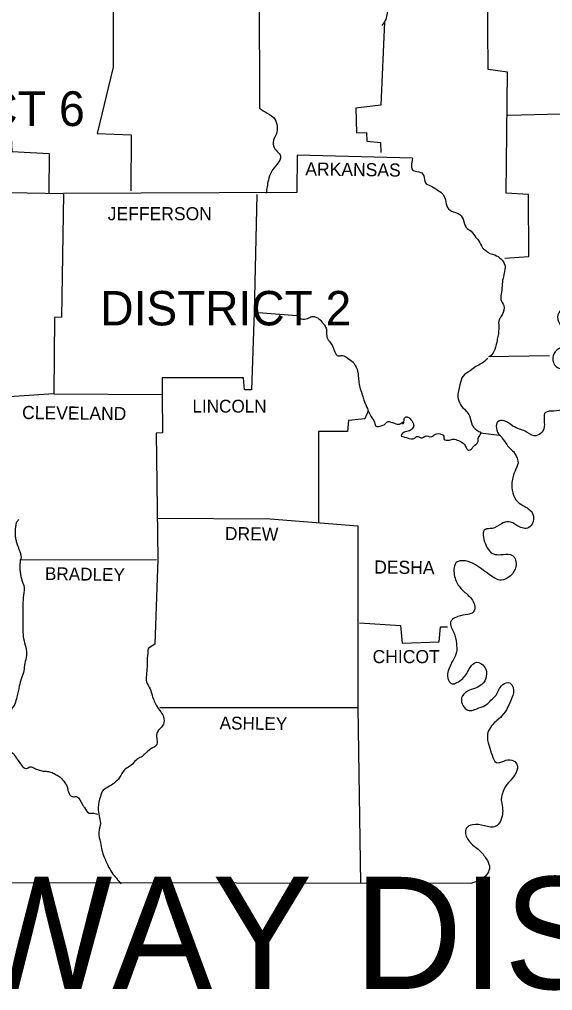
# Model space of a CAD drawing. Extents: x -43543 to 34500, y -13675 to 11152.
# Drawn here: x 13557 to 15268, y 4715 to 7833 of the extents above; entities that cross this region are included whole.
import ezdxf

# ---------------------------------------------------------------- set-up
doc = ezdxf.new("R2010")
doc.units = 0
for name, color, linetype in [('1', 7, 'Continuous'), ('2', 7, 'Continuous'), ('3', 7, 'Continuous')]:
    doc.layers.add(name, color=color, linetype=linetype)

msp = doc.modelspace()

# ---------------------------------------------------------------- linework, layer by layer
at = {"layer": '1'}
msp.add_line((15062.2, 6750.6), (15257.9, 6753.5), dxfattribs=at)
for points in [[(14186.6, 8101.8), (14188.5, 7926.6), (14326.5, 7923.7), (14327.4, 7548)], [(13800.1, 8056.8), (13856.8, 8052.9), (13857.8, 7679.1), (13806.9, 7466.8), (13915.5, 7461.9), (13914.6, 7281.9)], [(15115.1, 7066.6), (15191.4, 7071.5), (15190.4, 7270.1), (15119, 7275), (15122.9, 7663.4), (15061.3, 7672.3), (15059.3, 7933.5), (15893.9, 7939.4)], [(14728.6, 7824.9), (14716.9, 7556.8), (14636.6, 7548), (14638.6, 7468.7), (14670.9, 7469.7), (14671.8, 7442.3), (14715.9, 7437.4), (14716.9, 7405.1)], [(13044.8, 7812.2), (13154.3, 7805.3), (13150.4, 7683), (13278.6, 7678.1), (13280.6, 7571.5), (13341.2, 7566.6), (13341.2, 7548), (13398, 7544.1), (13399.9, 7475.6), (13529.1, 7475.6), (13533, 7408.1), (13652.3, 7402.2), (13651.4, 7275)], [(15124.9, 7525.5), (15676.7, 7539.2)], [(14818.6, 7387.5), (14448.8, 7397.3), (14446.8, 7277), (13698.3, 7274)], [(13134.8, 7144.9), (13189.6, 7152.7), (13193.5, 7186), (13225.8, 7191.9), (13227.7, 7211.4), (13455.7, 7218.3), (13464.5, 7278), (13698.3, 7274)], [(13698.3, 7272.1), (13692.5, 6876.8), (13670, 6875.8), (13667, 6630.3)], [(14318.6, 7271.1), (14310.8, 6892.5), (14446.8, 6881.7)], [(14310.8, 6892.5), (14302, 6643.9), (14279.5, 6643.9), (14275.6, 6682.1), (14015.3, 6682.1), (14015.3, 6627.3)], [(13667, 6630.3), (13524.2, 6621.4)], [(13667, 6630.3), (14015.3, 6628.3)], [(14015.3, 6628.3), (14016.3, 6506), (13995.8, 6505), (14001.6, 6099)], [(14676.7, 6576.4), (14665, 6550), (14613.1, 6545.1), (14610.2, 6509.9), (14517.3, 6509.9), (14516.3, 6217.4)], [(14786.3, 6533.4), (14789.3, 6536.3), (14792.2, 6539.3), (14792.2, 6539.3)], [(13998.7, 6232), (14361.7, 6229.1), (14643.5, 6207.6)], [(14643.5, 6207.6), (14643.5, 5622.5), (14651.3, 5059.9)], [(13559.4, 6098), (13996.5, 6099)], [(14001.6, 6099), (13991.9, 5827), (13970.3, 5813.3)], [(14648.4, 5895.5), (14779.5, 5887.6), (14785.3, 5830.9), (14903.7, 5834.8), (14908.6, 5882.7), (14931.1, 5882.7)], [(14007.5, 5623.5), (14643.5, 5623.5)], [(12742, 5063.6), (15008.4, 5059.9)]]:
    msp.add_lwpolyline(points, dxfattribs=at)
for points in [[(14717.8, 7918.8), (14713.9, 7899.2), (14721.7, 7878.7), (14735.4, 7871.8), (14737.4, 7852.3), (14732.5, 7832.7), (14728.6, 7824.9), (14719.8, 7813.1)], [(15832.2, 7702.6), (15809.7, 7674.2), (15776.5, 7691.8), (15776.5, 7715.3), (15781.4, 7739.8), (15769.6, 7755.4), (15749.1, 7748.6), (15749.1, 7718.2), (15747.1, 7688.9), (15741.2, 7646.8), (15754.9, 7634.1), (15786.3, 7630.2), (15808.8, 7624.3), (15822.5, 7601.8), (15821.5, 7574.4), (15810.7, 7548), (15795.1, 7526.5), (15770.6, 7518.6), (15751, 7531.4), (15743.2, 7556.8), (15734.4, 7579.3), (15717.8, 7595.9), (15700.2, 7577.3), (15696.2, 7543.1), (15697.2, 7513.8), (15697.2, 7473.6), (15722.7, 7447.2), (15738.3, 7416.9), (15733.4, 7389.5), (15714.8, 7357.2), (15707, 7328.8), (15699.2, 7290.7), (15700.2, 7248.6), (15693.3, 7207.5), (15679.6, 7180.1), (15654.2, 7157.6), (15637.5, 7142.9), (15623.8, 7128.3), (15617, 7098.9), (15612.1, 7078.4), (15593.5, 7053.9), (15578.8, 7051.9), (15567.1, 7061.7), (15563.2, 7078.4), (15563.2, 7095), (15555.4, 7111.6), (15530.9, 7118.5), (15511.3, 7117.5), (15502.5, 7103.8), (15515.2, 7065.6), (15520.1, 7041.2), (15513.3, 7007.9), (15517.2, 7004), (15482, 6985.4), (15453.6, 6982.5), (15430.1, 6975.6), (15407.6, 6961), (15396.8, 6939.4), (15381.2, 6921.8), (15367.5, 6905.2), (15348.9, 6897.4), (15328.4, 6901.3), (15301, 6904.2), (15285.3, 6884.6), (15290.2, 6856.3), (15308.8, 6839.6), (15336.2, 6831.8), (15364.6, 6833.8), (15392, 6836.7), (15417.4, 6823), (15412.5, 6796.6), (15388, 6783.9), (15351.8, 6779.9), (15322.5, 6782.9), (15287.3, 6775.1), (15269.7, 6752.6), (15279.4, 6718.3), (15317.6, 6704.6), (15335.2, 6672.3), (15336.2, 6642), (15323.5, 6601.9), (15305.9, 6583.3), (15271.6, 6575.5), (15245.2, 6570.6), (15241.3, 6525.6), (15229.5, 6503.1), (15209, 6496.2), (15179.6, 6510.9), (15162, 6517.7), (15140.5, 6527.5), (15113.1, 6544.2), (15092.6, 6541.2), (15098.4, 6498.2), (15100.4, 6496.2), (15123.9, 6463.9), (15147.4, 6438.5), (15158.1, 6408.2)], [(14327.4, 7548), (14351.9, 7531.4), (14377.3, 7511.8), (14384.2, 7485.4), (14382.2, 7466.8), (14374.4, 7451.1), (14372.5, 7426.7), (14384.2, 7409.1), (14395, 7394.4), (14384.2, 7368), (14365.6, 7343.5), (14355.8, 7316.1), (14349, 7275)], [(14818.6, 7387.5), (14821.5, 7347.4), (14845, 7341.6), (14854.8, 7330.8), (14859.7, 7308.3), (14876.3, 7298.5), (14898.8, 7284.8), (14912.5, 7275), (14922.3, 7259.4), (14928.2, 7233.9), (14943.8, 7217.3), (14965.4, 7209.5), (14981, 7190.9), (14990.8, 7164.5), (15006.5, 7152.7), (15022.1, 7132.2), (15029.9, 7123.4), (15043.6, 7099.9), (15057.3, 7088.1), (15067.1, 7081.3), (15082.8, 7076.4), (15102.3, 7063.7), (15115.1, 7044.1), (15115.1, 7029.4), (15110.2, 7006.9), (15106.3, 6983.5), (15104.3, 6957), (15102.3, 6933.6), (15111.2, 6914), (15106.3, 6884.6), (15096.5, 6869), (15095.5, 6847.5), (15092.6, 6815.2), (15088.7, 6796.6), (15079.8, 6766.2), (15067.1, 6750.6)], [(14446.8, 6881.7), (14461.5, 6871.9), (14482, 6872.9), (14495.7, 6878.8), (14506.5, 6877.8), (14521.2, 6869), (14531, 6857.2), (14537.8, 6848.4), (14542.7, 6834.7), (14542.7, 6822), (14547.6, 6804.4), (14553.5, 6797.6), (14561.3, 6784.8), (14566.2, 6773.1), (14569.1, 6765.3), (14579.9, 6752.6), (14589.7, 6753.5), (14598.5, 6752.6), (14610.2, 6745.7), (14627.8, 6732), (14630.8, 6728.1), (14642.5, 6702.7), (14644.5, 6687), (14646.4, 6666.5), (14650.3, 6646.9), (14658.2, 6625.4), (14662.1, 6610.7), (14670.9, 6590.1), (14676.7, 6576.4), (14684.6, 6558.8), (14696.3, 6539.3), (14701.2, 6527.5), (14717.8, 6528.5), (14729.6, 6533.4), (14738.4, 6541.2), (14749.1, 6540.2), (14760.9, 6536.3), (14776.5, 6533.4), (14786.3, 6539.3), (14791.2, 6543.2), (14792.2, 6552), (14801, 6556.9), (14810.8, 6550), (14821.5, 6534.4), (14821.5, 6524.6), (14817.6, 6518.7), (14804.9, 6510.9), (14787.3, 6505), (14782.4, 6498.2), (14799, 6490.3), (14825.5, 6488.4), (14832.3, 6494.3), (14849.9, 6489.4), (14856.8, 6494.3), (14880.2, 6493.3), (14891, 6501.1), (14912.5, 6500.1), (14919.4, 6495.2), (14919.4, 6486.4), (14937, 6482.5), (14949.7, 6485.4), (14966.3, 6480.6), (14981, 6472.7), (14988.9, 6462), (14998.6, 6450.2), (15007.4, 6453.2), (15014.3, 6462), (15029, 6477.6), (15029, 6487.4), (15032.9, 6494.3), (15037.8, 6504)], [(15060.3, 6744.7), (15039.7, 6728.1), (15022.1, 6718.3), (15003.5, 6704.6), (14981, 6688), (14970.3, 6659.6), (14964.4, 6620.5), (14972.2, 6597), (14989.8, 6576.4), (15001.6, 6559.8), (15010.4, 6530.5), (15031.9, 6509.9), (15038.8, 6507)], [(15158.1, 6408.2), (15148.3, 6385.6), (15137.6, 6346.5), (15140.5, 6313.2), (15155.2, 6284.9), (15178.7, 6269.2), (15204.1, 6246.7), (15202.1, 6212.5), (15187.5, 6199.8), (15153.2, 6208.6), (15126.8, 6220.3), (15104.3, 6213.4), (15074, 6198.8), (15051.5, 6195.8), (15052.4, 6148.9), (15082.8, 6115.6), (15109.2, 6115.6), (15139.5, 6111.7), (15150.3, 6076.5), (15132.7, 6047.1), (15103.3, 6032.4), (15066.1, 6050.1), (15039.7, 6068.6), (15013.3, 6086.3), (14980, 6095.1), (14961.5, 6091.1), (14952.7, 6050.1), (14968.3, 6012.9), (14993.7, 5987.4), (15017.2, 5954.2), (15013.3, 5929.7), (14995.7, 5922.9), (14964.4, 5916), (14945.8, 5906.2), (14940.9, 5898.4), (14950.7, 5865.1), (14959.5, 5828.9), (14959.5, 5801.5), (14948.7, 5776.1), (14932.1, 5737), (14934.1, 5711.5), (14945.8, 5699.8), (14960.5, 5703.7), (14980, 5717.4), (14992.8, 5733.1), (15003.5, 5752.6), (15024.1, 5769.3), (15049.5, 5754.6), (15055.4, 5724.2), (15040.7, 5697.8), (15020.2, 5686.1), (14994.7, 5676.3), (14976.1, 5654.8), (14981, 5629.3), (14995.7, 5615.6), (15031.9, 5622.5), (15056.4, 5633.3), (15070.1, 5647), (15086.7, 5663.6), (15095.5, 5680.2), (15108.2, 5697.8), (15130.7, 5702.7), (15141.5, 5688), (15137.6, 5654.8), (15123.9, 5623.5), (15105.3, 5597.1), (15084.7, 5578.5), (15059.3, 5538.3), (15064.2, 5501.2), (15074, 5470.8), (15087.7, 5447.4), (15111.2, 5452.2), (15137.6, 5455.2), (15153.2, 5442.5), (15151.3, 5415.1), (15131.7, 5388.7), (15113.1, 5363.2), (15103.3, 5328), (15107.2, 5303.5), (15107.2, 5281), (15099.4, 5256.6), (15085.7, 5242.9), (15049.5, 5243.8), (15011.4, 5247.8), (14990.8, 5236), (14994.7, 5202.8), (15017.2, 5178.3), (15032.9, 5165.6), (15055.4, 5138.2), (15065.2, 5115.7), (15062.2, 5096.1), (15048.5, 5079.5), (15008.4, 5059.9)], [(13553.5, 6227.3), (13551.5, 6223.6), (13549.1, 6220), (13547, 6216.3), (13545.7, 6212.5), (13545, 6207.7), (13544.3, 6202.8), (13543.3, 6193), (13543, 6183.1), (13543.7, 6173.3), (13546.1, 6160), (13549.6, 6146.9), (13551.4, 6142), (13553.5, 6137.1), (13555.5, 6132.3), (13557.4, 6127.3), (13559.3, 6121.8), (13560.8, 6116.2), (13561.8, 6110.5), (13562.2, 6107.6), (13562.3, 6104.8), (13561.6, 6101.3), (13560.6, 6099.6), (13559.4, 6098)], [(13559.4, 6098), (13563.3, 6037.3), (13572.1, 6008), (13569.2, 5976.7), (13568.2, 5946.3), (13568.2, 5918.9), (13568.2, 5892.5), (13568.2, 5865.1), (13570.2, 5845.6), (13577, 5817.2), (13579.9, 5790.8), (13574.1, 5765.3), (13571.1, 5741.9), (13563.3, 5718.4), (13556.5, 5692), (13548.6, 5657.7), (13541.8, 5635.2), (13528.1, 5611.7), (13519.3, 5590.2), (13505.6, 5576.5), (13503.6, 5553), (13506.6, 5531.5), (13504.6, 5511.9), (13511.5, 5493.3), (13529.1, 5480.6)], [(13970.3, 5813.3), (13967.4, 5783), (13966.4, 5754.6), (13964.5, 5727.2), (13964.5, 5706.6), (13976.2, 5684.1), (13983.1, 5662.6), (13989.9, 5644), (14003.6, 5619.6), (14016.3, 5601), (14020.2, 5574.5), (14012.4, 5560.9), (13997.7, 5540.3), (13996.7, 5503.1), (13979.1, 5491.4), (13956.6, 5471.8), (13943.9, 5463), (13930.2, 5454.2), (13915.5, 5438.6), (13894, 5423.9), (13878.4, 5399.4), (13860.7, 5380.8), (13846.1, 5371), (13825.5, 5358.3), (13816.7, 5338.8), (13809.9, 5302.6), (13812.8, 5276.1), (13816.7, 5252.7), (13811.8, 5223.3), (13816.7, 5191), (13821.6, 5165.6), (13829.4, 5143.1), (13840.2, 5117.6), (13853.9, 5094.2), (13883.3, 5058)], [(12994.9, 5587.3), (13010.5, 5598), (13025.2, 5603.9), (13039.9, 5601), (13055.5, 5599), (13069.2, 5601), (13086.8, 5598), (13101.5, 5589.2), (13118.1, 5582.4), (13134.8, 5582.4), (13149.4, 5582.4), (13162.2, 5573.6), (13185.6, 5574.5), (13205.2, 5582.4), (13224.8, 5588.2), (13251.2, 5591.2), (13274.7, 5574.5), (13291.3, 5560.9), (13305, 5545.2), (13314.8, 5527.6), (13325.6, 5517.8), (13343.2, 5511), (13356.9, 5508), (13373.5, 5503.1), (13382.3, 5499.2), (13390.1, 5480.6), (13402.9, 5455.2), (13427.3, 5446.4), (13457.6, 5458.1), (13482.1, 5465), (13499.7, 5470.8), (13510.5, 5474.8), (13520.3, 5475.7), (13517.3, 5477.7), (13529.1, 5480.6), (13539.8, 5472.8), (13546.7, 5462), (13558.4, 5446.4), (13569.2, 5432.7), (13579.9, 5427.8), (13590.7, 5433.7), (13605.4, 5428.8), (13618.1, 5423.9), (13632.8, 5420), (13645.5, 5419), (13662.1, 5415.1), (13674.9, 5408.2), (13686.6, 5401.4), (13698.3, 5388.7), (13710.1, 5369.1), (13714, 5353.4), (13727.7, 5337.8), (13740.4, 5337.8), (13759, 5312.3), (13765.8, 5302.6), (13780.5, 5284.9), (13791.3, 5284.9), (13808.2, 5281.7)]]:
    msp.add_spline(points, degree=3, dxfattribs=at)
at = {"layer": '3'}
msp.add_line((15035.8, 6506), (15097.5, 6498.2), dxfattribs=at)

# ---------------------------------------------------------------- texts
at = {"layer": '2'}
for s, height, rotation, p in [('ARKANSAS', 42.06, 359.2678, (14474.2, 7331.8)), ('CLEVELAND', 42.07, 359.3377, (13565.3, 6550)), ('DREW', 42.06, 359.2258, (14215.9, 6161.6)), ('DESHA', 42.06, 359.3704, (14695.3, 6054)), ('BRADLEY', 41.08, 359.1449, (13638.7, 6033.4)), ('ASHLEY', 41.09, 359.2361, (14199.3, 5554))]:
    msp.add_text(s, height=height, rotation=rotation, dxfattribs=at).set_placement(p)
for s, height, p in [('JEFFERSON', 42.07, (13840.2, 7187.9)), ('LINCOLN', 41.09, (14112.2, 6570.6)), ('CHICOT', 42.07, (14690.4, 5766.3)), ('ARKANSAS HIGHWAY DISTRICTS 3 & 7', 360, (9441.3, 4720.5))]:
    msp.add_text(s, height=height, dxfattribs=at).set_placement(p)
at = {"layer": '3'}
for s, height, p in [('DISTRICT 6', 111.54, (12954.7, 7490.3)), ('DISTRICT 2', 110.56, (13816.7, 6850.4))]:
    msp.add_text(s, height=height, dxfattribs=at).set_placement(p)

doc.saveas('drawing.dxf')
